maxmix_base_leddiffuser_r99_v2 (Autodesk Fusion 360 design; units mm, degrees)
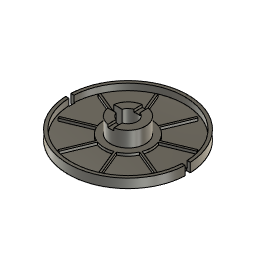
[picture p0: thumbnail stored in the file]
sketch "Sketch1" plane through (0, 0, 0) normal (0, 0, 1) x axis (1, 0, 0)
  circle C1 centre (0, 0) radius 22.95
  circle C2 centre (0, 0) radius 21.75
  circle C3 centre (0, 0) radius 6.7
  circle C4 centre (0, 0) radius 9.125
  circle C5 centre (0, 0) radius 3.6
  point P1 (0, 0)
  point P2 (0, 0)
  point P3 (0, 0)
  coincident P1 P2
  coincident P1 P3
  concentric C2 C3
  concentric C1 C4
  concentric C4 C5
  dimension "d1" diameter C1 = 45.9
  dimension "d2" diameter C2 = 43.5
  dimension "d3" diameter C4 = 18.25
  dimension "d4" diameter C3 = 13.4
  dimension "d5" diameter C5 = 7.2
extrude "Extrude1" new body sketch "Sketch1" profile of C2 C4 along normal blind 1
extrude "Extrude2" add sketch "Sketch1" profile of C3 C4 along normal blind 2
extrude "Extrude3" add sketch "Sketch1" profile of C1 C2 along normal blind 3.5
extrude "Extrude4" add sketch "Sketch1" profile of C3 C5 along normal blind 7.9
sketch "Sketch2" plane through (0, 0, 7.9) normal (0, 0, 1) x axis (-1, 0, 0)
  line L1 (0, 22.95) -> (0, -22.95)
  line L2 (-22.95, 0) -> (22.95, 0)
  line L3 (1.15, 6.6006) -> (1.15, 3.4114)
  line L4 (-1.15, 6.6006) -> (-1.15, 3.4114)
  line L5 (-1.15, -6.6006) -> (-1.15, -3.4114)
  line L6 (1.15, -6.6006) -> (1.15, -3.4114)
  line L7 (-21.5, -1) -> (-22.9282, -1)
  line L8 (-21.5, 1) -> (-21.5, -1)
  line L9 (-22.9282, 1) -> (-21.5, 1)
  line L10 (21.5, -1) -> (22.9282, -1)
  line L11 (21.5, 1) -> (21.5, -1)
  line L12 (22.9282, 1) -> (21.5, 1)
  line L13 (6.6006, -1.15) -> (3.4114, -1.15)
  line L14 (3.4114, 1.15) -> (6.6006, 1.15)
  circle C1 centre (0, 0) radius 3.6
  circle C2 centre (0, 0) radius 6.7
  circle C3 centre (0, 0) radius 22.95
  point P1 (0, 0)
  point P4 (-22.95, 0)
  point P5 (0, 22.95)
  point P6 (22.95, 0)
  point P7 (0, -22.95)
  point P8 (1.15, 3.4114)
  point P9 (1.15, 6.6006)
  point P10 (-1.15, 3.4114)
  point P11 (-1.15, 6.6006)
  point P12 (-1.15, -3.4114)
  point P13 (-1.15, -6.6006)
  point P14 (1.15, -3.4114)
  point P16 (-22.9282, -1)
  point P19 (-22.9282, 1)
  point P20 (22.9282, -1)
  point P23 (22.9282, 1)
  point P15 (1.15, -6.6006)
  point P24 (3.4114, -1.15)
  point P25 (6.6006, -1.15)
  point P26 (6.6006, 1.15)
  point P27 (3.4114, 1.15)
  vertical L1
  horizontal L2
  coincident P1 L1
  coincident P1 L2
  coincident C3 P4
  coincident C3 P5
  coincident C3 P6
  coincident C3 P7
  coincident C1 P8
  coincident C2 P9
  vertical L3
  coincident C1 P10
  coincident C2 P11
  parallel L1 L4
  coincident C1 P12
  coincident C2 P13
  parallel L4 L5
  coincident C1 P14
  parallel L1 L6
  coincident C3 P16
  perpendicular L1 L7
  perpendicular L7 L8
  coincident C3 P19
  perpendicular L1 L9
  coincident C3 P20
  parallel L2 L10
  perpendicular L10 L11
  coincident C3 P23
  perpendicular L11 L12
  symmetric L2 L10 L12
  symmetric L2 L7 L9
  symmetric L1 L5 L6
  collinear L4 L5
  collinear L7 L10
  symmetric L1 L8 L11
  coincident C2 P15
  coincident C1 P24
  coincident C2 P25
  horizontal L13
  coincident C2 P26
  coincident C1 P27
  parallel L2 L14
  symmetric L2 L13 L14
  dimension "d14" distance L3 L4 = 2.3
  dimension "d15" distance L7 L9 = 2
  dimension "d16" distance P1 L11 = 21.5
  dimension "d28" distance L13 L14 = 2.3 (= "d14")
extrude "Extrude5" cut sketch "Sketch2" profile of C3 L7 L8 L9 L10 L11 L12 no distance stored
extrude "Extrude6" cut sketch "Sketch2" profile of C1 C2 L3 L4 L5 L6 against normal blind 1
extrude "Extrude7" cut sketch "Sketch2" profile of C1 C2 L13 L14 to an object
sketch "Sketch3" plane through (0, 0, 1) normal (0, 0, 1) x axis (-1, 0, 0)
  line L1 (21.727, 1) -> (21.5, 1)
  line L2 (-21.5, 1) -> (-21.727, 1)
  line L3 (-21.5, -1) -> (-21.5, 1)
  line L4 (-21.727, -1) -> (-21.5, -1)
  line L5 (21.5, -1) -> (21.727, -1)
  line L6 (21.5, 1) -> (21.5, -1)
  line L7 (-7.8067, -18.8471) -> (0, 0)
  line L8 (-7.4357, -18.9966) -> (-3.1191, -8.5754)
  line L9 (-3.8582, -8.2692) -> (-8.1748, -18.6904)
  line L10 (0, -20) -> (0, -2.5)
  arc A1 centre (0, 0) radius 21.75 clockwise from (-21.727, 1) to (21.727, 1)
  arc A2 centre (0, 0) radius 21.75 clockwise from (21.727, -1) to (-21.727, -1)
  circle C1 centre (0, 0) radius 9.125
  circle C2 centre (0, 0) radius 9.125
  circle C3 centre (0, 0) radius 20.4
  point P1 (0, 0)
  point P12 (0, 0)
  point P14 (0, 0)
  point P13 (-7.8067, -18.8471)
  point P15 (-3.1191, -8.5754)
  point P16 (-7.4357, -18.9966)
  point P17 (-8.1748, -18.6904)
  point P18 (-3.8582, -8.2692)
  coincident P1 P12
  coincident P1 P14
  coincident P13 C3
  coincident C2 P15
  coincident C3 P16
  coincident C3 P17
  coincident C2 P18
  parallel L8 L9
  symmetric L7 L8 L9
  dimension "d22" diameter C3 = 40.8
  dimension "d23" distance L8 L9 = 0.8
  dimension "d29" angle L7 L10 = 22.5
extrude "Extrude8" add sketch "Sketch3" profile of C1 C2 C3 L8 L9 to an object
circular_pattern "C-Pattern1" TotalAngle 360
